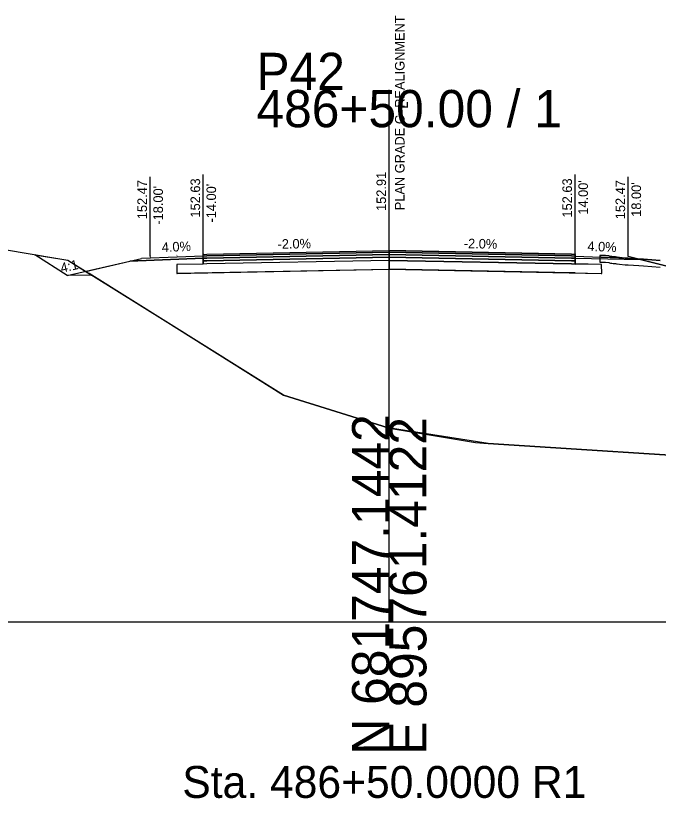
# Model space of a CAD drawing. Extents: x -26 to 4303, y -13 to 10775.
# Drawn here: x 3121.9 to 3170.3, y 4986.7 to 5045.6 of the extents above; entities that cross this region are included whole.
import ezdxf

# ---------------------------------------------------------------- set-up
doc = ezdxf.new("R2010")
doc.units = 0
for name, color, linetype in [('_CIVIL_CONSTRUCTION', 7, 'Continuous'), ('ASHPALT_12_5MM1', 7, 'Continuous'), ('Default', 7, 'Continuous'), ('Draft_XS_Text', 7, 'Continuous'), ('DTM CONTOURS_MAJOR', 7, 'Continuous'), ('DTM_P_FINISHED_GRADE', 7, 'Continuous'), ('DTM_TEMP_DROP', 7, 'Continuous'), ('DTM_X_BOUNDARY', 7, 'Continuous'), ('DTM_X_GROUND', 7, 'Continuous'), ('X_ROW', 7, 'Continuous'), ('XS_CELL', 7, 'Continuous'), ('XS_P_ASPHALT', 7, 'Continuous'), ('XS_P_DR_GRAVEL', 7, 'Continuous'), ('XS_P_GROUND', 7, 'Continuous'), ('XS_P_SUBGRADE_GRANULAR', 7, 'Continuous'), ('XS_P_SUBGRADE_LEVELING', 7, 'Continuous'), ('XS_P_SUBGRADE_MILLING', 7, 'Continuous'), ('XS_P_TX_CLEARZONE', 7, 'Continuous'), ('XS_P_TX_FS_BS', 7, 'Continuous'), ('XS_SHEET_EW_TX_AREA', 7, 'Continuous')]:
    doc.layers.add(name, color=color, linetype=linetype)

msp = doc.modelspace()

# ---------------------------------------------------------------- linework, layer by layer
for points in [[(3136.272, 5027.349), (3150, 5027.623), (3150, 5027.439), (3150, 5027.436), (3136.272, 5027.161), (3136, 5027.156), (3136, 5027.159), (3136, 5027.343), (3136.272, 5027.349)], [(3163.728, 5027.349), (3150, 5027.623), (3150, 5027.439), (3150, 5027.436), (3163.728, 5027.161), (3164, 5027.156), (3164, 5027.159), (3164, 5027.343), (3163.728, 5027.349)]]:
    msp.add_lwpolyline(points)
at = {"layer": 'ASHPALT_12_5MM1'}
for p, q in [((3150, 5027.79), (3136, 5027.51)), ((3136, 5027.343), (3136, 5027.51)), ((3136, 5027.343), (3136, 5027.492)), ((3164, 5027.51), (3150, 5027.79)), ((3164, 5027.343), (3164, 5027.51))]:
    msp.add_line(p, q, dxfattribs=at)
at = {"layer": 'Default'}
for points in [[(3136.272, 5027.515), (3150, 5027.79), (3150, 5027.626), (3150, 5027.623), (3136.272, 5027.349), (3136, 5027.343), (3136, 5027.346), (3136, 5027.51), (3136.272, 5027.515)], [(3163.728, 5027.515), (3150, 5027.79), (3150, 5027.626), (3150, 5027.623), (3163.728, 5027.349), (3164, 5027.343), (3164, 5027.346), (3164, 5027.51), (3163.728, 5027.515)]]:
    msp.add_lwpolyline(points, dxfattribs=at)
at = {"layer": 'DTM_P_FINISHED_GRADE'}
msp.add_lwpolyline([(3165.856, 5027.561), (3165.904, 5027.559), (3166.022, 5027.554), (3166.107, 5027.551), (3166.117, 5027.55), (3166.133, 5027.55), (3166.177, 5027.548), (3166.24, 5027.545), (3166.25, 5027.545), (3166.29, 5027.543), (3166.528, 5027.514), (3166.59, 5027.49), (3166.658, 5027.483), (3166.66, 5027.483), (3166.695, 5027.479), (3166.759, 5027.472), (3166.856, 5027.459), (3166.903, 5027.454), (3166.983, 5027.445), (3167.028, 5027.44), (3167.107, 5027.431), (3167.151, 5027.426), (3167.339, 5027.408), (3167.776, 5027.359), (3167.787, 5027.358), (3167.79, 5027.358), (3167.799, 5027.357), (3167.82, 5027.354), (3167.836, 5027.353), (3167.871, 5027.349), (3167.897, 5027.348), (3168, 5027.341), (3168.796, 5027.287), (3169.146, 5027.262), (3170.398, 5027.182)], dxfattribs=at)
at = {"layer": 'DTM_X_GROUND'}
msp.add_lwpolyline([(3121.043, 5028.008), (3124.888, 5027.357), (3125.792, 5027.191), (3133.123, 5022.647), (3142.048, 5017.046), (3149.924, 5014.592), (3150.011, 5014.564), (3156.484, 5013.493), (3157.461, 5013.398), (3177.004, 5012.157), (3200.167, 5011.663), (3206.976, 5011.327), (3212.719, 5011.146), (3225.338, 5011.067), (3261.632, 5010.739), (3284.436, 5011.007), (3300, 5011.444)], dxfattribs=at)
at = {"layer": 'X_ROW'}
for p, q in [((3136, 5027.51), (3134.037, 5027.431)), ((3136, 5027.348), (3136, 5027.51)), ((3164, 5027.51), (3168.595, 5027.326)), ((3136, 5027.343), (3130.47, 5027.122)), ((3130.47, 5027.122), (3131.344, 5027.324)), ((3134.037, 5027.431), (3131.344, 5027.324)), ((3136, 5027.343), (3136, 5027.348)), ((3164, 5027.343), (3168.925, 5027.244)), ((3168.925, 5027.244), (3168.595, 5027.326))]:
    msp.add_line(p, q, dxfattribs=at)
for points in [[(3134.04, 5026.2), (3136.078, 5026.241), (3136.349, 5026.246), (3150, 5026.519), (3150, 5026.532), (3150, 5027.186), (3136.272, 5026.911), (3136, 5026.906), (3134.053, 5026.879), (3134.014, 5026.878), (3134, 5026.212), (3134, 5026.199), (3134.04, 5026.2)], [(3165.96, 5026.2), (3166, 5026.199), (3166, 5026.212), (3165.986, 5026.878), (3165.947, 5026.879), (3164, 5026.906), (3163.728, 5026.911), (3150, 5027.186), (3150, 5026.532), (3150, 5026.519), (3163.651, 5026.246), (3163.922, 5026.241), (3165.96, 5026.2)]]:
    msp.add_lwpolyline(points, dxfattribs=at)
at = {"layer": 'XS_CELL'}
for p, q in [((3150, 5000), (3150, 5040)), ((3000, 5000), (3150, 5000)), ((3150, 5000), (3300, 5000))]:
    msp.add_line(p, q, dxfattribs=at)
at = {"layer": 'XS_P_ASPHALT'}
msp.add_lwpolyline([(3136.272, 5027.64), (3150, 5027.915), (3163.728, 5027.64), (3164, 5027.635), (3164, 5026.92), (3164, 5026.906), (3163.728, 5026.911), (3150, 5027.186), (3136.272, 5026.911), (3136, 5026.906), (3136, 5026.92), (3136, 5027.635), (3136.272, 5027.64)], dxfattribs=at)
at = {"layer": 'XS_P_DR_GRAVEL'}
for points in [[(3165.856, 5027.561), (3165.856, 5027.061), (3165.904, 5027.059), (3166.022, 5027.054), (3166.107, 5027.051), (3166.117, 5027.05), (3166.133, 5027.05), (3166.177, 5027.048), (3166.24, 5027.045), (3166.25, 5027.045), (3166.29, 5027.043), (3166.528, 5027.014), (3166.59, 5026.99), (3166.658, 5026.983), (3166.66, 5026.983), (3166.695, 5026.979), (3166.759, 5026.972), (3166.856, 5026.959), (3166.903, 5026.954), (3166.983, 5026.945), (3167.028, 5026.94), (3167.107, 5026.931), (3167.151, 5026.926), (3167.339, 5026.908), (3167.776, 5026.859), (3167.787, 5026.858), (3167.79, 5026.858), (3167.799, 5026.857), (3167.82, 5026.854), (3167.836, 5026.853), (3167.871, 5026.849), (3167.897, 5026.848), (3168, 5026.841), (3168, 5026.841), (3168, 5026.841), (3168.796, 5026.787), (3169.146, 5026.762), (3170.398, 5026.682)], [(3170.398, 5027.182), (3169.146, 5027.262), (3168.796, 5027.287), (3168, 5027.341), (3168, 5027.341), (3168, 5027.341), (3167.897, 5027.348), (3167.871, 5027.349), (3167.836, 5027.353), (3167.82, 5027.354), (3167.799, 5027.357), (3167.79, 5027.358), (3167.787, 5027.358), (3167.776, 5027.359), (3167.339, 5027.408), (3167.151, 5027.426), (3167.107, 5027.431), (3167.028, 5027.44), (3166.983, 5027.445), (3166.903, 5027.454), (3166.856, 5027.459), (3166.759, 5027.472), (3166.695, 5027.479), (3166.66, 5027.483), (3166.658, 5027.483), (3166.59, 5027.49), (3166.528, 5027.514), (3166.29, 5027.543), (3166.25, 5027.545), (3166.24, 5027.545), (3166.177, 5027.548), (3166.133, 5027.55), (3166.117, 5027.55), (3166.107, 5027.551), (3166.022, 5027.554), (3165.904, 5027.559), (3165.856, 5027.561)]]:
    msp.add_lwpolyline(points, dxfattribs=at)
at = {"layer": 'XS_P_GROUND'}
msp.add_line((3125.756, 5026.035), (3123.311, 5027.603), dxfattribs=at)
for points in [[(3220.13, 5011.099), (3180.781, 5024.215), (3180, 5024.475), (3179.766, 5024.533), (3168, 5027.475)], [(3125.756, 5026.035), (3130.47, 5027.122)]]:
    msp.add_lwpolyline(points, dxfattribs=at)
at = {"layer": 'XS_P_SUBGRADE_GRANULAR'}
for points in [[(3136, 5026.239), (3136.272, 5026.245), (3150, 5026.519)], [(3164, 5026.239), (3163.728, 5026.245), (3150, 5026.519)]]:
    msp.add_lwpolyline(points, dxfattribs=at)
at = {"layer": 'XS_P_SUBGRADE_LEVELING'}
for points in [[(3136.272, 5027.64), (3150, 5027.915), (3150, 5027.792), (3150, 5027.79), (3136.272, 5027.515), (3136, 5027.51), (3136, 5027.512), (3136, 5027.635), (3136.272, 5027.64)], [(3163.728, 5027.64), (3150, 5027.915), (3150, 5027.792), (3150, 5027.79), (3163.728, 5027.515), (3164, 5027.51), (3164, 5027.512), (3164, 5027.635), (3163.728, 5027.64)]]:
    msp.add_lwpolyline(points, dxfattribs=at)
at = {"layer": 'XS_P_SUBGRADE_MILLING'}
for points in [[(3136.272, 5027.161), (3150, 5027.436), (3150, 5027.191), (3150, 5027.186), (3136.272, 5026.911), (3136, 5026.906), (3136, 5026.911), (3136, 5027.156), (3136.272, 5027.161)], [(3163.728, 5027.161), (3150, 5027.436), (3150, 5027.191), (3150, 5027.186), (3163.728, 5026.911), (3164, 5026.906), (3164, 5026.911), (3164, 5027.156), (3163.728, 5027.161)]]:
    msp.add_lwpolyline(points, dxfattribs=at)
at = {"layer": 'XS_P_TX_CLEARZONE'}
for p, q in [((3132, 5027.475), (3132, 5033.475)), ((3132, 5027.475), (3132, 5033.475)), ((3136, 5027.635), (3136, 5033.635)), ((3136, 5027.635), (3136, 5033.635)), ((3136, 5027.635), (3136, 5033.635)), ((3150, 5027.915), (3150, 5033.915)), ((3150, 5027.915), (3150, 5033.915)), ((3164, 5027.635), (3164, 5033.635)), ((3164, 5027.635), (3164, 5033.635)), ((3168, 5027.475), (3168, 5033.475)), ((3168, 5027.475), (3168, 5033.475))]:
    msp.add_line(p, q, dxfattribs=at)
at = {"layer": 'XS_SHEET_EW_TX_AREA'}
for points in [[(3127.58, 5026.069), (3125.756, 5026.035), (3123.311, 5027.603), (3125.34, 5027.274), (3125.792, 5027.191)], [(3220.13, 5011.099), (3212.719, 5011.146), (3203.572, 5011.495), (3188.585, 5011.91), (3177.004, 5012.157), (3157.461, 5013.398), (3149.924, 5014.592), (3142.048, 5017.046), (3127.413, 5026.186), (3127.141, 5026.354), (3130.47, 5027.122), (3136, 5027.343), (3136, 5026.906), (3134.007, 5026.872), (3134, 5026.212), (3150, 5026.519), (3166, 5026.199), (3165.986, 5026.878), (3164, 5026.911), (3164, 5027.343), (3168.925, 5027.244), (3180, 5024.475)]]:
    msp.add_lwpolyline(points, close=True, dxfattribs=at)

# ---------------------------------------------------------------- texts
at = {"layer": '_CIVIL_CONSTRUCTION'}
for p in [(3133.961, 5027.495), (3133.961, 5027.479), (3133.961, 5027.479), (3133.961, 5027.479), (3133.961, 5027.479), (3133.961, 5027.479), (3133.961, 5027.479), (3135.961, 5027.575), (3135.961, 5027.575), (3135.961, 5027.575), (3135.961, 5027.575), (3135.961, 5027.575), (3135.961, 5027.575), (3135.961, 5027.575), (3131.018, 5027.179), (3131.018, 5027.179), (3131.018, 5027.179), (3131.039, 5027.184), (3131.039, 5027.184), (3131.039, 5027.184)]:
    msp.add_text('X', height=0.12, dxfattribs=at).set_placement(p)
at = {"layer": 'Draft_XS_Text'}
msp.add_text('Sta. 486+50.0000 R1', height=2.4, dxfattribs=at).set_placement((3134.42, 4986.75))
at = {"layer": 'DTM CONTOURS_MAJOR'}
for p in [(3135.961, 5027.575), (3149.961, 5027.855), (3163.961, 5027.575)]:
    msp.add_text('X', height=0.12, dxfattribs=at).set_placement(p)
at = {"layer": 'DTM_TEMP_DROP'}
for p in [(3131.961, 5027.415), (3131.961, 5027.383), (3131.961, 5027.383), (3131.961, 5027.383), (3131.961, 5027.383), (3131.961, 5027.383)]:
    msp.add_text('X', height=0.12, dxfattribs=at).set_placement(p)
at = {"layer": 'DTM_X_BOUNDARY'}
for p in [(3131.961, 5027.415), (3131.961, 5027.415), (3167.961, 5027.415)]:
    msp.add_text('X', height=0.12, dxfattribs=at).set_placement(p)
at = {"layer": 'XS_CELL'}
for s, p in [('P42', (3140, 5040)), ('486+50.00 / 1', (3140, 5037.2))]:
    msp.add_text(s, height=2.8, dxfattribs=at).set_placement(p)
for s, p in [('N 681747.1442', (3150, 4990)), ('E 895761.4122', (3152.8, 4990))]:
    msp.add_text(s, height=2.8, rotation=90, dxfattribs=at).set_placement(p)
at = {"layer": 'XS_P_TX_CLEARZONE'}
for s, p in [('PLAN GRADE C  REALIGNMENT', (3151.152, 5030.955)), ('L', (3151.402, 5038.6)), ('152.91', (3149.76, 5030.9)), ('152.91', (3149.76, 5030.9)), ('152.47', (3131.76, 5030.279)), ('152.47', (3131.76, 5030.279)), ('152.63', (3135.76, 5030.405)), ('152.63', (3135.76, 5030.405)), ('152.63', (3135.76, 5030.405)), ("-14.00'", (3136.96, 5030.031)), ("-14.00'", (3136.96, 5030.031)), ("-14.00'", (3136.96, 5030.031)), ('152.63', (3163.76, 5030.405)), ('152.63', (3163.76, 5030.405)), ("14.00'", (3164.96, 5030.62)), ("14.00'", (3164.96, 5030.62)), ('152.47', (3167.76, 5030.279)), ('152.47', (3167.76, 5030.279)), ("18.00'", (3168.96, 5030.46)), ("18.00'", (3168.96, 5030.46)), ("-18.00'", (3132.96, 5029.871)), ("-18.00'", (3132.96, 5029.871))]:
    msp.add_text(s, height=0.72, rotation=90, dxfattribs=at).set_placement(p)
at = {"layer": 'XS_P_TX_FS_BS'}
for s, rotation, p in [('-2.0%', 1.14576, (3141.598, 5028.047)), ('-2.0%', 358.85424, (3155.61, 5028.103)), ('4.0%', 2.29061, (3132.887, 5027.811)), ('4.0%', 357.70939, (3164.911, 5027.899)), ('4:1', 12.99192, (3125.336, 5026.245))]:
    msp.add_text(s, height=0.72, rotation=rotation, dxfattribs=at).set_placement(p)

doc.saveas('drawing.dxf')
